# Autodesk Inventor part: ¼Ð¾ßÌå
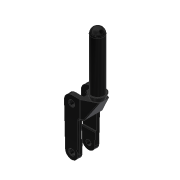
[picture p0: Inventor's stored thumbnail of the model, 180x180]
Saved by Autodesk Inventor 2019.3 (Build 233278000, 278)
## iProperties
Created: 2017-10
Part Number: ¼Ð¾ßÌå
Material: Ogólny
Document SubType Name: Modeling
Designer: CADENGINEERING4
Density: 1 g/cm^3
Appearance: Gładki — czarny
Author: CADENGINEERING4
Revision Number: ÈÎºÎ
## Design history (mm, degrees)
feature "Ô²½Ç7"
node "Bryła1"
